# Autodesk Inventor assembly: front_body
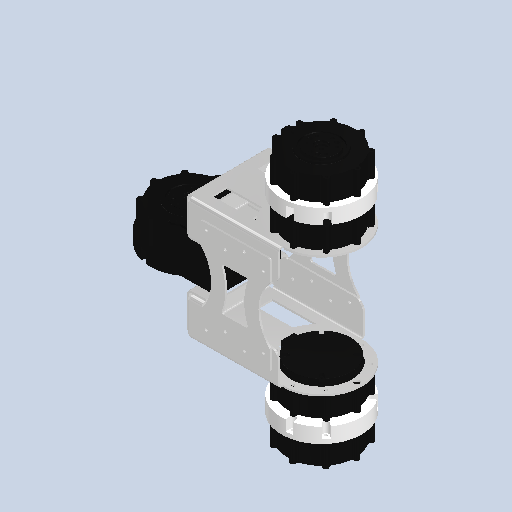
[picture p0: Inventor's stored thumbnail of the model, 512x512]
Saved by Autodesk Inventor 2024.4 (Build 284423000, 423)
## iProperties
Created: 2026-01
Part Number: front_body
Document SubType Name: Assembly
Designer: AdminForWorker
Title: front_body v2
Author: AdminForWorker
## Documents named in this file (2)
- c:\worker\convert-fusion-r06-cosv3\tmp\job-1\14\temp\files\7069be28-f26d-4d32-a85d-de0caccc6a05\516abab2-e13c-41df-b98f-88082b7d1051.iam
- c:\worker\convert-fusion-r06-cosv3\tmp\job-1\14\temp\files\7069be28-f26d-4d32-a85d-de0caccc6a05\hind_body v18.iam
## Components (1 placed, 1 different names)
1. hind_body v18:1 [sub-assembly]
